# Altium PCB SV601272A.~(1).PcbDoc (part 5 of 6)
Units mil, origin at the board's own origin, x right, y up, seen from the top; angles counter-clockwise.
Board outline 8300 x 9520 mil, 8 copper layers (Top Layer, Signal Layer 1, Signal Layer 2, Signal Layer 3, Signal Layer 4, Signal Layer 5, Signal Layer 6, Bottom Layer), stack 59.2 mil thick; 551 components, 303 nets, 1611 pads, 1923 vias.
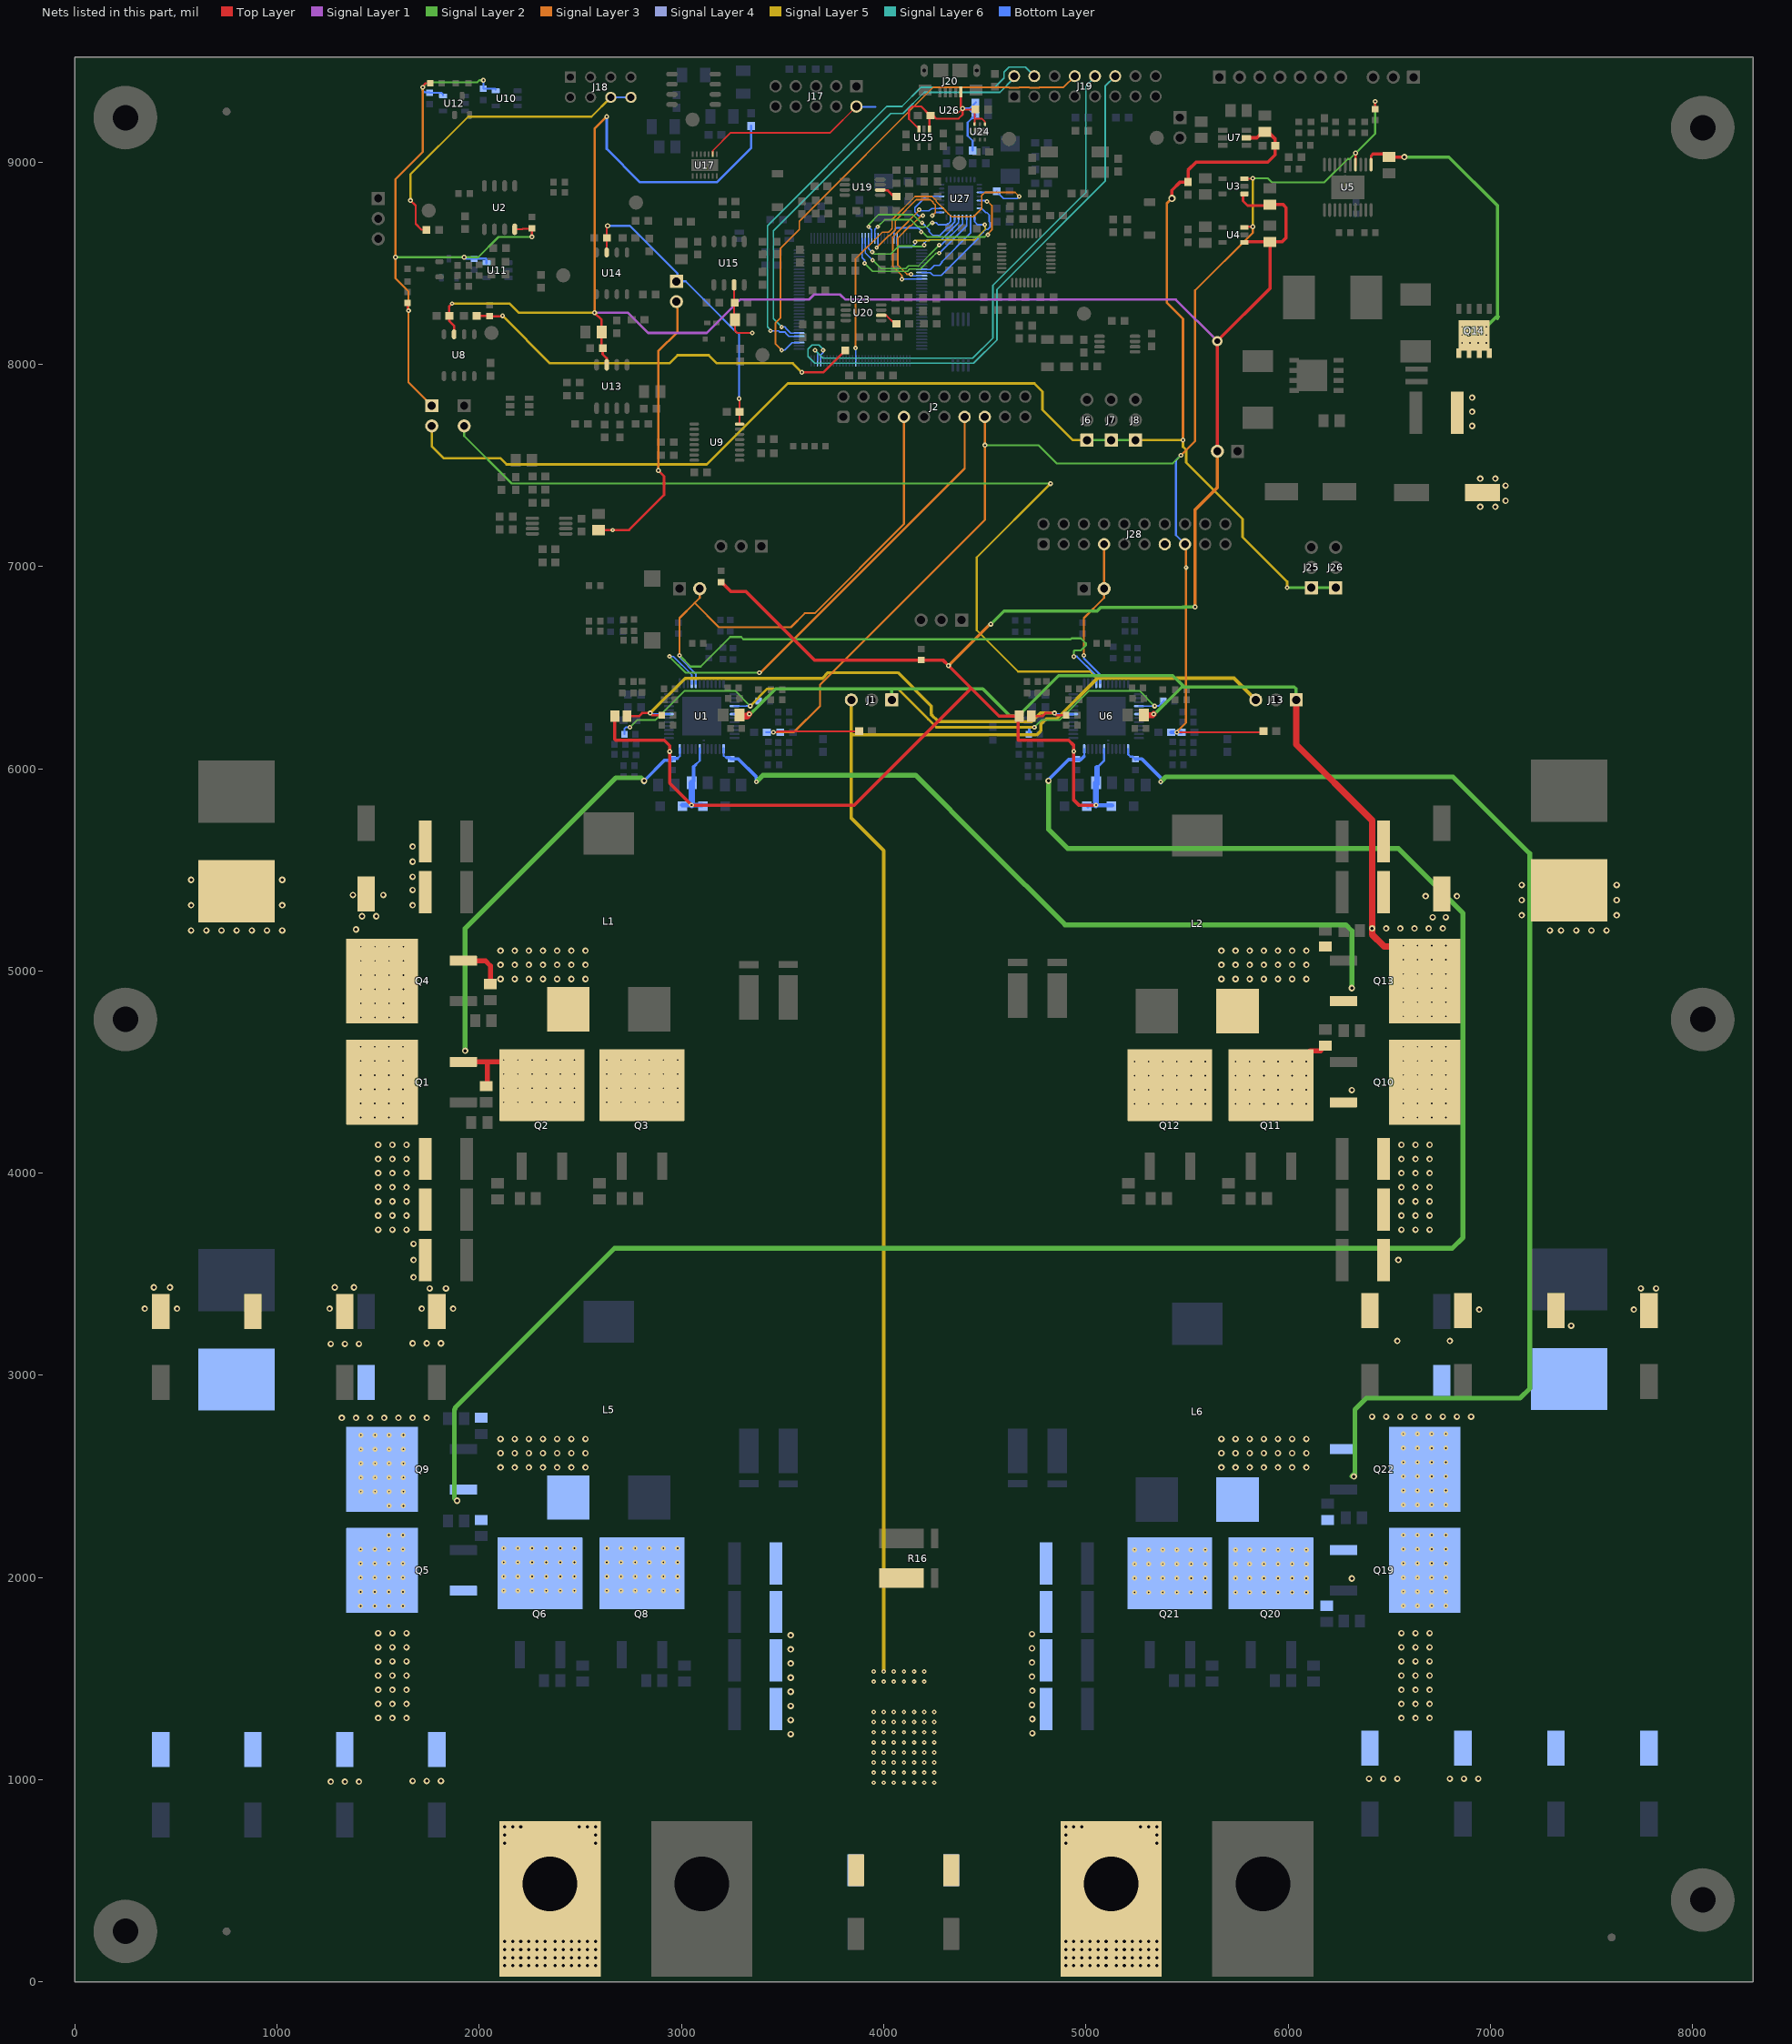
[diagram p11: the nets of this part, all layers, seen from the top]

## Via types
v1: diameter 32, hole 16, Top Layer to Bottom Layer, tented both sides, 622 vias
v2: diameter 24, hole 8, Top Layer to Bottom Layer, 380 vias
v3: diameter 22, hole 8, Top Layer to Bottom Layer, tented both sides, 346 vias
v4: diameter 32, hole 16, Top Layer to Bottom Layer, 237 vias
v5: diameter 24, hole 10, Top Layer to Bottom Layer, tented both sides, 153 vias
v6: diameter 19.68, hole 7.87, Top Layer to Bottom Layer, 70 vias
v7: diameter 24, hole 10, Top Layer to Bottom Layer, 47 vias
v8: diameter 28, hole 8, Top Layer to Bottom Layer, tented top, 24 vias
v9: diameter 22, hole 8, Top Layer to Bottom Layer, 19 vias
v10: diameter 19.68, hole 8, Top Layer to Bottom Layer, 16 vias
v11: diameter 50, hole 28, Top Layer to Bottom Layer, 4 vias
v12: diameter 36, hole 20, Top Layer to Bottom Layer, 2 vias
v13: diameter 26, hole 12, Top Layer to Bottom Layer, 1 vias
v14: diameter 28, hole 12, Top Layer to Bottom Layer, tented both sides, 1 vias
v15: diameter 24, hole 10, Top Layer to Bottom Layer, tented top, 1 vias

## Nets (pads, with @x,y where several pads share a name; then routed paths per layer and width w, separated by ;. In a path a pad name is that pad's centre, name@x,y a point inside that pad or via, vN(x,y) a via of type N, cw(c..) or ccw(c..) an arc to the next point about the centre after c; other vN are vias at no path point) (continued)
SPI_DONE: J19.12 U23.29 | length 2730.5
  Signal Layer 6 w8: v3(3700,8070) 3700,8075 3680,8095 3645,8095 3625,8075 3625,8040 3660,8005 4445,8005 4560,8120 4560,8370 5095,8905 5095,9375 J19.12@5145,9425
  Bottom Layer w6: U23.29@3689.09,8020 3689.09,8046.61 3700,8057.52 v3(3700,8070)
SPI_DRDY: J19.10 U23.30 | length 2500.5
  Signal Layer 6 w8: v3(3660,8070) 3700,8030 4440,8030 4540,8130 4540,8390 5000,8850 5000,9375 5045,9420 J19.10@5045,9425
  Bottom Layer w6: v3(3660,8070) 3672.4,8057.6 U23.30@3672.4,8016.85
SPI_MISO: J19.2 U23.38 | length 2123.7
  Signal Layer 4 w8: J19.2@4645,9405 J19.2@4645,9425
  Signal Layer 6 w8: v3(3495,8185) 3455,8225 3455,8660 4035,9240 4095,9240 4200,9345 4575,9345 4645,9415 J19.2@4645,9425
  Bottom Layer w6: 3520,8175 3540.35,8154.65 U23.38@3581.85,8154.65
  Bottom Layer w8: v3(3495,8185) 3510,8185 3520,8175
SPI_MOSI: J19.4 U23.37 | length 2360.2
  Signal Layer 6 w8: v3(3440,8165) 3440,8170 3425,8185 3425,8685 4015,9275 4090,9275 4185,9370 4550,9370 4595,9415 4595,9445 4620,9470 4700,9470 J19.4@4745,9425
  Bottom Layer w6: 3520,8150 3531.1,8138.9 U23.37@3581.85,8138.9
  Bottom Layer w8: v3(3440,8165) 3480,8165 3485,8160 3510,8160 3520,8150
SPI_SCLK: J19.8 U23.35 | length 2464.4
  Signal Layer 3 w8: v3(3495,8070) 3465,8100 3465,8205 3490,8230 3490,8574.25 3582.87,8667.13 3582.87,8707.87 4245,9370 4619,9370 4621.28,9367.72 4668.72,9367.72 4671,9370 4719,9370 4721.28,9367.72 4768.72,9367.72 4771,9370 4890,9370 J19.8@4945,9425
  Bottom Layer w6: v3(3495,8070) 3510,8070 3547.4,8107.4 U23.35@3581.85,8107.4
SW1: C7.1 L1.1 Q1.3 Q2.4 Q3.4 Q4.3 R22.1 R29.1 U1.24 | length 2634.9
  Top Layer w24: Q1.3@1920.33,4550 2115,4550 Q2.4@2125,4560 ; Q4.3@1935,5050 2030,5050 2055,5025 R29.1@2055,4935 ; R22.1@2040,4425 2040,4550
  Signal Layer 2 w24: v1(1930,4605) 1930,5209.92 2675.08,5955 2800,5955 v1(2815,5940)
  Bottom Layer w9.8: 2980,6050 2991.73,6061.73 U1.24@2991.73,6101.54
  Bottom Layer w16: v1@2815,5930 v1(2815,5940) 2917.56,6042.56 C7.1@2950,6042.56 ; C7.1@2950,6045 2955,6050 2980,6050
  other v1: 2105,4960 2175,4960 2245,4960 2315,4960 2385,4960 2455,4960 2525,4960 2105,5030 2175,5030 2245,5030 2315,5030 2385,5030 2455,5030 2525,5030 2105,5100 2175,5100 2245,5100 2315,5100 2385,5100 2455,5100 2525,5100
  other v2: 2120.63,4349.92 2190.63,4349.92 2260.63,4349.92 2330.63,4349.92 2400.63,4349.92 2470.63,4349.92 2630.63,4349.92 2700.63,4349.92 2770.63,4349.92 2840.63,4349.92 2910.63,4349.92 2980.63,4349.92 2120.63,4419.92 2190.63,4419.92 2260.63,4419.92 2330.63,4419.92 2400.63,4419.92 2470.63,4419.92 2630.63,4419.92 2700.63,4419.92 2770.63,4419.92 2840.63,4419.92 2910.63,4419.92 2980.63,4419.92 2120.63,4489.92 2190.63,4489.92 2260.63,4489.92 2330.63,4489.92 2400.63,4489.92 2470.63,4489.92 2630.63,4489.92 2700.63,4489.92 2770.63,4489.92 2840.63,4489.92 2910.63,4489.92 2980.63,4489.92 2120.63,4559.92 2190.63,4559.92 2260.63,4559.92 2330.63,4559.92 2400.63,4559.92 2470.63,4559.92 2630.63,4559.92 2700.63,4559.92 2770.63,4559.92 2840.63,4559.92 2910.63,4559.92 2980.63,4559.92
SW2: C12.2 L2.2 Q10.3 Q11.4 Q12.4 Q13.3 R33.2 R40.2 U1.13 | length 3975.2
  Top Layer w24: Q11.4@6090,4550 v2(6090,4551.81) 6090,4585 6110,4605 6160,4605 R33.2@6185,4630
  Signal Layer 2 w24: v5(3370,5935) 3403.13,5968.13 4156.87,5968.13 4506.33,5618.67 4506.33,5618.59 4896.8,5228.13 6285,5228.13 6315,5198.13 v4(6315,4915)
  Bottom Layer w9.8: U1.13@3208.27,6101.54 3208.27,6064.32 3222.79,6055
  Bottom Layer w16: 3222.79,6055 3237.56,6055 C12.2@3245,6047.56 3281.91,6047.56 3370,5959.47 v5(3370,5935)
  other v1: 5670,4960 5740,4960 5810,4960 5880,4960 5950,4960 6020,4960 6090,4960 5670,5030 5740,5030 5810,5030 5880,5030 5950,5030 6020,5030 6090,5030 5670,5100 5740,5100 5810,5100 5880,5100 5950,5100 6020,5100 6090,5100
  other v2: 5240,4341.81 5310,4341.81 5380,4341.81 5450,4341.81 5520,4341.81 5590,4341.81 5740,4341.81 5810,4341.81 5880,4341.81 5950,4341.81 6020,4341.81 6090,4341.81 5240,4411.81 5310,4411.81 5380,4411.81 5450,4411.81 5520,4411.81 5590,4411.81 5740,4411.81 5810,4411.81 5880,4411.81 5950,4411.81 6020,4411.81 6090,4411.81 5240,4481.81 5310,4481.81 5380,4481.81 5450,4481.81 5520,4481.81 5590,4481.81 5740,4481.81 5810,4481.81 5880,4481.81 5950,4481.81 6020,4481.81 6090,4481.81 5240,4551.81 5310,4551.81 5380,4551.81 5450,4551.81 5520,4551.81 5590,4551.81 5740,4551.81 5810,4551.81 5880,4551.81 5950,4551.81 6020,4551.81
  other v4: 6315,4410
SW3: C192.1 L5.2 Q5.3 Q6.4 Q8.4 Q9.3 R174.1 R182.1 U6.24 | length 10135.5
  Signal Layer 2 w24: v4(1890,2380) 1876.87,2393.13 1876.87,2831.14 1880.87,2835.14 1880.87,2840.87 2668.13,3628.13 6811.33,3628.13 6865,3681.8 ; v1(4815,5940) 4815,5700.08 4910.08,5605 4973.75,5605 ; 4980,5605 6545,5605 6548.13,5601.87 6548.2,5601.87 6865,5285.08 6865,3681.8 ; 6865,3690 6865,3681.8
  Bottom Layer w9.8: 4991.73,6061.73 U6.24@4991.73,6097.6
  Bottom Layer w16: v1@4810,5940 4915,6045 4975,6045 4991.73,6061.73
  other v1: 2105,2545 2175,2545 2245,2545 2315,2545 2385,2545 2455,2545 2525,2545 2105,2615 2175,2615 2245,2615 2315,2615 2385,2615 2455,2615 2525,2615 2105,2685 2175,2685 2245,2685 2315,2685 2385,2685 2455,2685 2525,2685
  other v2: 2120.63,1934.92 2190.63,1934.92 2260.63,1934.92 2330.63,1934.92 2400.63,1934.92 2470.63,1934.92 2630.63,1934.92 2700.63,1934.92 2770.63,1934.92 2840.63,1934.92 2910.63,1934.92 2980.63,1934.92 2120.63,2004.92 2190.63,2004.92 2260.63,2004.92 2330.63,2004.92 2400.63,2004.92 2470.63,2004.92 2630.63,2004.92 2700.63,2004.92 2770.63,2004.92 2840.63,2004.92 2910.63,2004.92 2980.63,2004.92 2120.63,2074.92 2190.63,2074.92 2260.63,2074.92 2330.63,2074.92 2400.63,2074.92 2470.63,2074.92 2630.63,2074.92 2700.63,2074.92 2770.63,2074.92 2840.63,2074.92 2910.63,2074.92 2980.63,2074.92 2120.63,2144.92 2190.63,2144.92 2260.63,2144.92 2330.63,2144.92 2400.63,2144.92 2470.63,2144.92 2630.63,2144.92 2700.63,2144.92 2770.63,2144.92 2840.63,2144.92 2910.63,2144.92 2980.63,2144.92
SW4: C195.2 L6.1 Q19.3 Q20.4 Q21.4 Q22.3 R185.2 R193.2 U6.13 | length 6144.5
  Signal Layer 2 w24: v5(5370,5935) 5395,5960 6814.92,5960 7195,5579.92 7195,2935.08 ; v4@6315,2500 6330,2515 6330,2830.08 6386.8,2886.87 7146.8,2886.87 7195,2935.08 ; 7195,2935 7195,2935.08
  Bottom Layer w9.8: U6.13@5208.27,6097.6 5208.27,6071.73 5220,6060
  Bottom Layer w12: 5220,6060 5230,6060 C195.2@5245,6045
  Bottom Layer w16: C195.2@5245,6047.56 5277.44,6047.56 5370,5955 v5(5370,5935) v5@5370,5930
  other v1: 6315,1995 5670,2545 5740,2545 5810,2545 5880,2545 5950,2545 6020,2545 6090,2545 5670,2615 5740,2615 5810,2615 5880,2615 5950,2615 6020,2615 6090,2615 5670,2685 5740,2685 5810,2685 5880,2685 5950,2685 6020,2685 6090,2685
  other v2: 5240,1926.81 5310,1926.81 5380,1926.81 5450,1926.81 5520,1926.81 5590,1926.81 5740,1926.81 5810,1926.81 5880,1926.81 5950,1926.81 6020,1926.81 6090,1926.81 5240,1996.81 5310,1996.81 5380,1996.81 5450,1996.81 5520,1996.81 5590,1996.81 5740,1996.81 5810,1996.81 5880,1996.81 5950,1996.81 6020,1996.81 6090,1996.81 5240,2066.81 5310,2066.81 5380,2066.81 5450,2066.81 5520,2066.81 5590,2066.81 5740,2066.81 5810,2066.81 5880,2066.81 5950,2066.81 6020,2066.81 6090,2066.81 5240,2136.81 5310,2136.81 5380,2136.81 5450,2136.81 5520,2136.81 5590,2136.81 5740,2136.81 5810,2136.81 5880,2136.81 5950,2136.81 6020,2136.81 6090,2136.81
  other v4: 6325,2500
SYNC: J2.7 J3.2 U1.41 U6.40 | length 4789.2
  Signal Layer 2 w10: v3(2990,6560) 3045,6505 3095,6505 3241.13,6651.13 3294.89,6651.13 3306.01,6640 4052.23,6640 4101.58,6640 4925,6640 4930,6645 4975,6645 5000,6620 5000,6610 4975,6585 4945,6585 4940,6580 v5(4940,6555)
  Signal Layer 3 w10: v3(2990,6560) 2990,6745 3065,6820 ; J3.2@3090,6890 3090,6845 3065,6820 ; J2.7@4100,7740 4100,7210.28 3658.6,6768.87 3610.11,6768.87 3541.24,6700 3185,6700 3065,6820
  Bottom Layer w8: v3@2985,6565 v3(2990,6560) 2990,6550 3070.38,6469.62 3070.38,6467.28 3070.47,6467.19 U1.41@3070.47,6418.46
  Bottom Layer w9.8: v5@4935,6555 v5(4940,6555) 4955,6555 5044.33,6465.67 5044.33,6465.37 5050.79,6458.91 U6.40@5050.79,6422.4
SYNCIN: J2.13 U1.40 | length 2360.6
  Signal Layer 2 w10: v3(2940,6555) 3020,6475 v5(3385,6475)
  Signal Layer 3 w10: v5@3385,6470 v5(3385,6475) ; v5@3390,6475 4400,7485 J2.13@4400,7740
  Bottom Layer w8: v3(2940,6555) 2960,6555 3050.79,6464.21 U1.40@3050.79,6418.46
SYNCIN2: J28.13
SYNCn: J17.2 U17.2 | length 913.6
  Top Layer w8: U17.2@3154.37,9039.13 3154.37,9055.61 3243.76,9145 3735,9145 J17.2@3865,9275
  Bottom Layer w8: J17.2@3865,9275 3866.5,9273.5 3960,9273.5
SYNCOUT2: J27.2 J28.7 U6.41 | length 757.4
  Signal Layer 3 w10: v5@4990,6570 4990,6745 5090,6845 J27.2@5090,6890 J28.7@5090,7110
  Bottom Layer w9.8: v5@4990,6565 v5(4990,6560) 4990,6545 5062,6473 5062,6472.69 5070.47,6464.22 U6.41@5070.47,6422.4
USB_VBUS: C179.1 C182.1 C187.2 C188.1 J20.1 R149.2 U24.4 U24.6 U25.1 U25.3 U26.6 | length 1197.9
  Top Layer w8: U26.6@4344.69,9243.19 4368.19,9243.19 4387.5,9262.5 v7(4390,9265) ; U24.6@4449.41,9188.39 C179.1@4449.41,9254.41 ; 4450,9215 4485,9215 4500.59,9199.41 U24.4@4500.59,9188.39
  Top Layer w10: U25.3@4174.41,9164.29 4125,9213.7 4125,9260 4140,9275 4185,9275 C182.1@4225,9235 ; U25.1@4225.59,9164.29 4225.59,9220.59 C182.1@4235,9230 ; C182.1@4231.5,9230 C182.1@4235,9230 ; J20.1@4381.18,9357.6 J20.1@4381.18,9347.6 4381.18,9273.82 v7(4390,9265) 4395,9260 C179.1@4453.5,9260 ; v7@4387.5,9262.5 4390,9260 4390,9235 4370,9215 4260,9215 4245,9230 C182.1@4235,9230 ; C179.1@4449.41,9254.41 C179.1@4450,9255 ; C179.1@4450,9250 C179.1@4450,9255 ; C179.1@4455,9260 C179.1@4450,9255
  Bottom Layer w10: v7(4390,9265) 4420,9265 ; R149.2@4440,9056.5 4440,9105 4415,9130 4415,9195 C187.2@4450,9230 ; C187.2@4453.5,9230 4420,9263.5 4420,9265 ; C188.1@4455,9295 4425,9265 4420,9265
USBCLK: U23.92 U27.1 | length 640.8
  Signal Layer 5 w8: v3(4155,8605) 4161.87,8611.87 4189.53,8611.87 ; 4189.53,8611.88 4210.47,8611.88 4221.88,8611.88 4225,8615 ; 4210.47,8611.87 4224.53,8611.87 4227.65,8615 4450,8615 4505,8670 4500,8675 v3(4500,8690)
  Bottom Layer w6: U23.92@4066.1,8623.15 4066.1,8588.9 4075,8580
  Bottom Layer w8: 4075.41,8580.41 4075.75,8580.75 4140.75,8580.75 4160.51,8600.51 v3@4160.51,8610 ; U27.1@4450,8725 4450,8705 4465,8690 v3(4500,8690)
USBD0: U23.81 U27.3 | length 790.3
  Signal Layer 2 w6: v3(3905,8500) 3945.75,8459.25 4114.81,8459.25 4115.56,8460 4118.13,8460 4128.13,8470 4180,8470 4245,8535
  Signal Layer 2 w8: v3@3905,8495 v3(3905,8500) ; 4245,8535 4260,8550 v3(4275,8550)
  Bottom Layer w6: U23.81@3892.87,8623.15 3892.87,8527.13 3900,8520
  Bottom Layer w8: 3900,8520 3905,8515 v3(3905,8500) ; v3(4275,8550) 4410,8685 U27.3@4410,8725 ; U27.3@4409.53,8725 U27.3@4409.53,8726.69
USBD1: U23.82 U27.4 | length 716.2
  Signal Layer 2 w6: v3(3945,8515) 3986.87,8473.13 4109.06,8473.13 4121.68,8485.75 4170.75,8485.75
  Signal Layer 2 w8: 4170.75,8485.75 v3(4275,8590)
  Bottom Layer w6: U23.82@3908.62,8623.15 3908.62,8551.38 3910,8550
  Bottom Layer w8: 3910,8550 v3(3945,8515) ; v3@4270,8585 v3(4275,8590) 4285,8590 4390,8695 U27.4@4390,8715 ; U27.4@4389.84,8715 U27.4@4389.84,8726.69
USBD2: U23.83 U27.5 | length 593.3
  Signal Layer 2 w8: v3(3942.88,8554.87) 3952.75,8545 4035,8545 4075,8585 4142.65,8585 4145.53,8582.13 4192.13,8582.13 v3@4200,8590
  Bottom Layer w6: U23.83@3924.37,8623.15 3924.37,8575.63 3925,8575
  Bottom Layer w8: 3925,8572.75 v3(3942.88,8554.87) ; v3(4200,8589) 4200,8600 4215,8615 4285,8615 4370,8700 U27.5@4370,8715
USBD3: U23.84 U27.6 | length 631.7
  Signal Layer 2 w8: v3(3925,8680) 3925,8690 3975,8740 4145,8740 4185,8700 v3(4190,8700) v3@4195,8695
  Bottom Layer w6: v3(3925,8680) 3940.12,8664.88 U23.84@3940.12,8623.15
  Bottom Layer w8: v3(3925,8680) v3@3930,8680 ; v3(4190,8700) 4225,8665 4225,8655 4242.87,8637.13 4270,8637.13 ; 4270,8635 4275.47,8635 4314.6,8674.13 4321.58,8674.13 4350.47,8703.02 U27.6@4350.47,8726.69
USBD4: U23.85 U27.7 | length 497.8
  Signal Layer 2 w6: 4168.13,8680 4179.07,8680 4180.94,8678.13 4199.06,8678.13 4200.93,8680 4215,8680
  Signal Layer 2 w8: v3(3970,8680) 4005,8715 4133.13,8715 4168.13,8680 ; 4215,8680 4235,8700 v3(4240,8700)
  Bottom Layer w6: U23.85@3955.87,8623.15 3955.87,8665.87 v3(3970,8680)
  Bottom Layer w8: v3@3965,8680 v3(3970,8680) ; v3(4240,8700) 4260,8700 4270,8690 4310,8690 4315,8695 4320,8695 4330,8705 ; 4330.79,8705.79 U27.7@4330.79,8726.69
USBD5: U23.86 U27.9 | length 585.3
  Signal Layer 3 w8: v3(3965.35,8576.75) 4025.85,8637.25 4029.7,8637.25 4034.7,8642.25 4035.64,8642.25 4057.75,8664.36 4057.75,8710.3 4161.58,8814.13 4230.87,8814.13 4244.13,8800.87 4244.13,8798.42 4255,8787.55 4255,8750 v3(4240,8735)
  Bottom Layer w6: v3@3965,8580 3971.61,8586.61 U23.86@3971.61,8623.15
  Bottom Layer w8: v3(4240,8735) 4256.1,8751.1 U27.9@4286.69,8751.1
USBD6: U23.106 U27.10 | length 636.4
  Signal Layer 3 w8: v3(4090,8420) 4090,8440 4045,8485 4045,8629.17 4073.62,8657.79 4073.62,8658.62 4175,8760 v3(4175,8765)
  Bottom Layer w6: v3(4090,8420) 4092.36,8422.36 U23.106@4188.15,8422.36 ; v3(4175,8765) 4181.87,8758.13 4224.16,8758.13 4236.82,8770.79 U27.10@4286.69,8770.79
USBD7: U23.105 U27.13 | length 670.9
  Signal Layer 3 w8: v3(4135,8445) 4115,8445 4070,8490 4070,8625 4130,8685 4135,8685 4185,8735 v3(4194.25,8735)
  Bottom Layer w6: v3(4135,8445) 4141.89,8438.11 U23.105@4188.15,8438.11 ; v3@4195,8735 v3(4194.25,8735) 4172.19,8735 4153.13,8754.07 4153.13,8774.06 4189.07,8810 4190,8810 4209.84,8829.84 U27.13@4286.69,8829.84
USBDIR: U23.104 U27.31 | length 569.8
  Bottom Layer w6: U23.104@4188.15,8453.86 4231.14,8453.86 4240,8445 ; U27.31@4473.31,8770.79 4484.54,8770.79 4505.33,8750 4510,8750
  Bottom Layer w8: 4240,8445 4245,8440 4285,8440 4465,8620 4465,8625 4492.13,8652.13 4492.13,8654.47 4504.78,8667.13 4514.47,8667.13 4527.84,8680.49 4526.94,8681.38 4526.94,8700.4 4521.87,8705.47 4521.87,8738.13 4511.21,8748.79
USBNXT: U23.103 U27.2 | length 396.7
  Bottom Layer w6: U23.103@4188.15,8469.61 4229.61,8469.61 4250,8490 4275,8490 4290,8505
  Bottom Layer w8: 4287.87,8505 4287.87,8507.87 4429.21,8649.21 U27.2@4429.21,8726.69
USBRST: R154.2 U23.18 U27.27 | length 1827.9
  Signal Layer 3 w8: v3(3860,8080) 3860,8520 3993.13,8653.13 4023.13,8653.13 4028.13,8658.13 4029.06,8658.13 4041.87,8670.94 4041.87,8716.87 4155,8830 4240,8830 4260,8810 4260,8805 4306.13,8758.87 4306.13,8758.27 4308.28,8756.12 4308.28,8756 4321,8743.28 4321.72,8743.28 4335,8730 4445,8730 4485,8770 4485,8835 4500,8850 4650,8850 v3(4670,8830)
  Bottom Layer w6: v3(3860,8080) 3861.38,8078.62 U23.18@3861.38,8016.85
  Bottom Layer w8: U27.27@4473.31,8849.53 4554.53,8849.53 R154.2@4559.25,8854.25 ; R154.2@4558.5,8855 R154.2@4559.25,8854.25 ; v3(4670,8830) 4660,8820 4593.5,8820 R154.2@4559.25,8854.25
USBSTP: U23.91 U27.29 | length 756.8
  Signal Layer 2 w8: v3(4185.73,8654.63) 4189.63,8654.63 4190,8655 4215,8630 4500,8630 4510,8640 v3(4515,8640)
  Signal Layer 3 w8: v3(4510,8805) 4515,8805 4535,8785 4535,8665 4515,8645 v3(4515,8640)
  Bottom Layer w6: U23.91@4050.35,8623.15 4050.35,8660.35 4065,8675
  Bottom Layer w8: 4065,8675 4170,8675 4185.73,8659.27 v3(4185.73,8654.63) ; U27.29@4473.31,8810.16 v3@4509.84,8810.16
UVLO: J2.15 J28.15 R4.1 R6.2 R34.1 R45.2 R53.1 R60.2 R87.2 U3.3 U4.3 U5.4 | length 8007.4
  Top Layer w10: v5@3450,6180 v5(3455,6180) 3470,6180 3475,6185 R4.1@3878.5,6185 R4.1@3882.44,6185 ; v5(5450,6180) 5875,6180 R34.1@5880,6185 ; U3.3@5777.24,8917.4 U3.3@5784.13,8917.4 5822.4,8917.4 v5(5825,8920) ; U4.3@5785,8680 v5(5825,8680) ; U5.4@6333.39,8987.2 v5@6333.39,9038.39 ; R53.1@6430,9265 v5(6430,9300)
  Signal Layer 2 w10: v5(4500,7600) 4765,7600 4855,7510 5430,7510 v7(5470,7550) ; v5(5825,8920) 5900,8920 5920,8900 6000,8900 6180.07,8900.07 6295,9015 6304.1,9015 v5(6334.1,9045) 6335,9045 6430,9140 v5(6430,9300)
  Signal Layer 3 w10: v5@3455,6175 3460,6180 3555,6180 3685,6310 3685,6415.56 4500,7230.56 v5(4500,7600) 4500,7715 J2.15@4505,7720 ; v5@5447.5,6180 5495,6227.5 v3(5495,6995) 5495,7080 J28.15@5490,7085 ; v7(5470,7550) 5540,7620 5540,8365 5825,8650 v5(5825,8680)
  Signal Layer 5 w10: v5(5825,8680) v5(5825,8920)
  Bottom Layer w10: R60.2@3417.56,6180 R60.2@3421.5,6180 v5(3455,6180) R6.2@3488.5,6180 R6.2@3490,6180 ; v7(5470,7550) 5445,7525 5445,7155 J28.15@5490,7110
  Bottom Layer w20: R45.2@5421.5,6180 v5(5450,6180) R87.2@5470,6180
V5: C99.2 C111.1 C116.1 C117.1 J14.1 U9.16 U14.7 U15.7 | length 1873.3
  Top Layer w10: U14.7@2630,8553.35 2630,8680 v13(2635,8685) ; C116.1@3255,8310 3260,8305 C117.1@3260,8220 ; U15.7@3260,8390 3260,8308.5 C116.1@3263.5,8305 ; C117.1@3265,8220 3265,8165 3275,8155 v5(3350,8155) ; C99.2@3285,7775 3287.2,7772.8 U9.16@3287.2,7704.57 ; C99.2@3286.5,7775 v5@3286.5,7828.5
  Bottom Layer w10: v13(2635,8685) 2745,8685 2980,8450 J14.1@2980,8410 ; J14.1@2975,8405 J14.1@2980,8410 ; 3280,8155 3285,8150 v5(3285,7830) ; v5(3350,8155) 3275,8155 3110,8320 3020,8410 J14.1@2980,8410
V5.0_Control: C76.1 J6.1 J7.1 J8.1 J14.2 J25.1 J26.1 J37.2 L7.2 R10.1 R164.2 U7.5 | length 8939
  Top Layer w12: L7.2@2590,7180 v3(2660,7180) 2740,7180 2913.65,7353.65 2913.65,7446.35 v7(2885,7475)
  Top Layer w16: v12(5425,8820) 5425,8860 5466.5,8901.5 R164.2@5505,8901.5 5505,8960 5545,9000 5900,9000 5935,9035 R10.1@5935,9075 ; U7.5@5790,9120 U7.5@5793.07,9120 5845,9120 5875,9150 C76.1@5885,9150 ; C76.1@5905,9145 5936.5,9113.5 R10.1@5936.5,9080
  Signal Layer 2 w12: J6.1@5005,7625 J7.1@5125,7625 J8.1@5245,7625 ; v3(5995,6895) J25.1@6115,6895 J26.1@6235,6895
  Signal Layer 3 w12: v7(2885,7475) 2885,8065 2980,8160 J14.2@2980,8315 ; v12(5425,8820) 5400,8795 5400,8305 5480,8225 v5(5480,7625)
  Signal Layer 5 w10: J6.1@5005,7625 J6.1@5015,7625
  Signal Layer 5 w12: J37.2@1765,7695 1765,7595 1825,7535 2105,7535 2120.13,7519.87 2120.3,7519.87 2134.87,7505.3 2134.87,7505 2885,7505 ; v7(2885,7475) 2885,7505 ; J6.1@5005,7625 4935,7625 4785,7775 4785,7865 4745,7905 3525,7905 3125,7505 2885,7505 ; J8.1@5245,7625 v5(5480,7625) 5480,7591.75 5495.87,7575.87 5495.87,7514.13 5775,7235 5775,7145 5995,6925 v3(5995,6895)
V5A: C84.1 C91.2 C93.1 C94.2 J37.1 R90.1 R91.1 U2.8 U10.5 U11.5 U12.5 | length 3298
  Top Layer w10: R90.1@1645,8300 1645,8270 v5(1650,8265) ; v5@1720,9375 1735,9390 R91.1@1757.44,9390 ; U2.8@2175,8667.72 2212.72,8667.72 2215,8670 2260,8670 v5(2260,8630)
  Signal Layer 2 w10: v5(1585,8530) v5(1925,8530) 1995,8530 2095,8630 v5(2260,8630) ; v5(1720,9370) 1745,9395 1990,9395 2000,9405 v5(2020,9405)
  Signal Layer 3 w10: v5(1720,9370) 1720,9050 1585,8915 v5(1585,8530) 1585,8425 1650,8360 v5(1650,8265) 1650,7910 J37.1@1765,7795
  Bottom Layer w10: v5(1720,9370) 1720,9355 1730,9345 C91.2@1755,9345 ; C91.2@1755,9342.56 1812.44,9342.56 1820,9335 U12.5@1820,9330 ; v5(1925,8530) 1932.44,8522.56 C93.1@1975,8522.56 2032.44,8522.56 2035,8520 U11.5@2035,8500 ; v5@2020,9395 C94.2@2020,9362.56 2077.44,9362.56 U10.5@2080,9360
V_HV: C6.1 C18.1 C22.1 C23.1 C24.1 C25.1 C32.1 C33.1 C38.1 C39.1 C40.1 C50.1 C51.1 C52.1 C53.1 C56.1 C57.1 C58.1 C59.1 C60.1 C61.1 C62.1 C63.1 C64.1 C65.1 C66.1 C67.1 C206.1 C207.1 C208.1 C209.1 C210.1 C211.1 C212.1 C213.1 C214.1 C215.1 C216.1 C217.1 J1.1 J9.1 J13.1 Q1.4 Q4.4 Q5.4 Q9.4 Q10.4 Q13.4 Q14.5 Q14.6 Q14.7 Q14.8 Q14.9 Q19.4 Q22.4 T1.1 U1.6 U5.1 U6.6 | length 6399.3
  Top Layer w10: C40.1@6485,9040 C40.1@6500,9025
  Top Layer w13: U5.1@6410.16,8987.2 6410.16,9030.16 6420,9040
  Top Layer w16: 6420,9040 C40.1@6485,9040 ; C40.1@6500,9025 v1(6575,9025)
  Top Layer w30: C33.1@5290,6265 5330,6265 v5(5334.84,6269.84)
  Top Layer w32: C6.1@3285.43,6260 3325,6260 v5(3334.84,6269.84) ; J13.1@6040,6345 J13.1@6040,6340 6040,6120 6415,5745 v1(6415,5210) 6415,5180 6475,5120 Q13.4@6570,5120
  Signal Layer 2 w16: v5(3334.84,6269.84) 3339.84,6269.84 3380,6310 ; 3382.5,6312.5 3465,6395 4040,6395 ; J1.1@4040,6340 4040,6395 ; v5@5339.84,6269.84 5474.18,6404.18 6030.75,6404.18 6040,6395.09 J13.1@6040,6340 ; 5485,6405 5430,6460 4865,6460 4665,6260 4625,6260 4490,6395 4040,6395 ; v1(6575,9025) 6795,9025 7035,8785 7035,8235 ; v8(6980,8185) 7030,8235 7035,8235 ; 7035,8225 7035,8235 ; 7040,8235 7035,8235
  Bottom Layer w9.8: U1.6@3258.46,6269.84 v5(3334.84,6269.84) ; U6.6@5262.4,6269.84 5330.16,6269.84 v5@5335,6265
  other v1: 1265,990 1335,990 1405,990 1670,993.24 1740,993.24 1810,993.24 6400,1005 6470,1005 6540,1005 6800,1005 6870,1005 6940,1005 1500,1305 1570,1305 1640,1305 6560,1305 6630,1305 6700,1305 1500,1375 1570,1375 1640,1375 6560,1375 6630,1375 6700,1375 1500,1445 1570,1445 1640,1445 6560,1445 6630,1445 6700,1445 1500,1515 1570,1515 1640,1515 6560,1515 6630,1515 6700,1515 1500,1585 1570,1585 1640,1585 6560,1585 6630,1585 6700,1585 1500,1655 1570,1655 1640,1655 6560,1655 6630,1655 6700,1655 1500,1725 1570,1725 1640,1725 6560,1725 6630,1725 6700,1725 1320,2790 1390,2790 1460,2790 1530,2790 1600,2790 1670,2790 1740,2790 6415,2795 6485,2795 6555,2795 6625,2795 6695,2795 6765,2795 6835,2795 6905,2795 1265,3155 1335,3155 1405,3155 1670,3158.24 1740,3158.24 1810,3158.24 6540,3170 6800,3170 7400,3245 6945,3325 7710,3325 345,3330 505,3330 1260,3330 1715,3330 1870,3330 1755,3430 1835,3430 7745,3430 7820,3430 390,3435 470,3435 1285,3435 1380,3435 1675,3485 1675,3570 6545,3570 1675,3650 1500,3720 1570,3720 1640,3720 6560,3720 6630,3720 6700,3720 1500,3790 1570,3790 1640,3790 6560,3790 6630,3790 6700,3790 1500,3860 1570,3860 1640,3860 6560,3860 6630,3860 6700,3860 1500,3930 1570,3930 1640,3930 6560,3930 6630,3930 6700,3930 1500,4000 1570,4000 1640,4000 6560,4000 6630,4000 6700,4000 1500,4070 1570,4070 1640,4070 6560,4070 6630,4070 6700,4070 1500,4140 1570,4140 1640,4140 6560,4140 6630,4140 6700,4140 575,5200 650,5200 725,5200 800,5200 875,5200 950,5200 1025,5200 7295,5200 7350,5200 7425,5200 7500,5200 7575,5200 1390,5205 6485,5210 6555,5210 6625,5210 6695,5210 6765,5210 6715,5265 6780,5265 1420,5270 1490,5270 7155,5275 7625,5275 575,5325 1025,5325 1670,5325 7155,5350 7625,5350 6680,5370 6835,5370 1375,5375 1525,5375 1670,5400 7155,5425 7625,5425 575,5450 1025,5450 1670,5465 1670,5540 1670,5615 6950,7295 7025,7295 7075,7325 7075,7400 6950,7435 7025,7435 6910,7695 6910,7765 6910,7835
  other v2: 1412.7,1859.45 1482.7,1859.45 1552.7,1859.45 1622.7,1859.45 6570,1860 6640,1860 6710,1860 6780,1860 1412.7,1929.45 1482.7,1929.45 1552.7,1929.45 1622.7,1929.45 6570,1930 6640,1930 6710,1930 6780,1930 1412.7,1999.45 1482.7,1999.45 1552.7,1999.45 1622.7,1999.45 6570,2000 6640,2000 6710,2000 6780,2000 1412.7,2069.45 1482.7,2069.45 1552.7,2069.45 1622.7,2069.45 6570,2070 6640,2070 6710,2070 6780,2070 1412.7,2139.45 1482.7,2139.45 1552.7,2139.45 1622.7,2139.45 6570,2140 6640,2140 6710,2140 6780,2140 1552.7,2209.45 1622.7,2209.45 6570,2210 6640,2210 6710,2210 6780,2210 1554.19,2354.37 1624.19,2354.37 6570,2360 6640,2360 6710,2360 6780,2360 1414.19,2424.37 1484.19,2424.37 1554.19,2424.37 1624.19,2424.37 6570,2430 6640,2430 6710,2430 6780,2430 1414.19,2494.37 1484.19,2494.37 1554.19,2494.37 1624.19,2494.37 6570,2500 6640,2500 6710,2500 6780,2500 1414.19,2564.37 1484.19,2564.37 1554.19,2564.37 1624.19,2564.37 6570,2570 6640,2570 6710,2570 6780,2570 1414.19,2634.37 1484.19,2634.37 1554.19,2634.37 1624.19,2634.37 6570,2640 6640,2640 6710,2640 6780,2640 1414.19,2704.37 1484.19,2704.37 1554.19,2704.37 1624.19,2704.37 6570,2710 6640,2710 6710,2710 6780,2710 1412.7,4274.45 1482.7,4274.45 1552.7,4274.45 1622.7,4274.45 6570,4275 6640,4275 6710,4275 6780,4275 1412.7,4344.45 1482.7,4344.45 1552.7,4344.45 1622.7,4344.45 6570,4345 6640,4345 6710,4345 6780,4345 1412.7,4414.45 1482.7,4414.45 1552.7,4414.45 1622.7,4414.45 6570,4415 6640,4415 6710,4415 6780,4415 1412.7,4484.45 1482.7,4484.45 1552.7,4484.45 1622.7,4484.45 6570,4485 6640,4485 6710,4485 6780,4485 1412.7,4554.45 1482.7,4554.45 1552.7,4554.45 1622.7,4554.45 6570,4555 6640,4555 6710,4555 6780,4555 1412.7,4624.45 1482.7,4624.45 1552.7,4624.45 1622.7,4624.45 6570,4625 6640,4625 6710,4625 6780,4625 1414.19,4769.37 1484.19,4769.37 1554.19,4769.37 1624.19,4769.37 6570,4775 6640,4775 6710,4775 6780,4775 1414.19,4839.37 1484.19,4839.37 1554.19,4839.37 1624.19,4839.37 6570,4845 6640,4845 6710,4845 6780,4845 1414.19,4909.37 1484.19,4909.37 1554.19,4909.37 1624.19,4909.37 6570,4915 6640,4915 6710,4915 6780,4915 1414.19,4979.37 1484.19,4979.37 1554.19,4979.37 1624.19,4979.37 6570,4985 6640,4985 6710,4985 6780,4985 1414.19,5049.37 1484.19,5049.37 1554.19,5049.37 1624.19,5049.37 6570,5055 6640,5055 6710,5055 6780,5055 1414.19,5119.37 1484.19,5119.37 1554.19,5119.37 1624.19,5119.37 6570,5125 6640,5125 6710,5125 6780,5125
  other v4: 2125,80 2165,80 2205,80 2245,80 2285,80 2325,80 2375,80 2415,80 2455,80 2495,80 2535,80 2575,80 2125,120 2165,120 2205,120 2245,120 2285,120 2325,120 2375,120 2415,120 2455,120 2495,120 2535,120 2575,120 2125,160 2165,160 2205,160 2245,160 2285,160 2325,160 2375,160 2415,160 2455,160 2495,160 2535,160 2575,160 2125,200 2165,200 2205,200 2245,200 2285,200 2325,200 2375,200 2415,200 2455,200 2495,200 2535,200 2575,200 2125,686.27 2575,686.27 2125,726.27 2575,726.27 2125,766.27 2165,766.27 2205,766.27 2495,766.27 2535,766.27 2575,766.27
  other v8: 6860,8105 6900,8105 6940,8105 6980,8105 6860,8145 6900,8145 6940,8145 6980,8145 6860,8185 6900,8185 6940,8185
V_LV: C20.1 C21.1 C26.1 C27.1 C28.1 C29.1 C54.1 C55.1 C68.1 C69.1 C70.1 C71.1 J1.3 J10.1 J13.3 J35.2 R16.2 T2.1 | length 11696.7
  Signal Layer 2 w10: J35.2@1925,7695 1925,7645 2160,7410 v7(4825,7410)
  Signal Layer 2 w16: J1.3@3840,6340 J1.3@3840,6366.13
  Signal Layer 5 w10: v7(4825,7410) 4460,7045 4460,6685 4665,6480 5020,6480 5054.71,6445.29 5055,6445
  Signal Layer 5 w16: J1.3@3840,6340 3840,6165 ; v3(4000,1535) 4000,5595 3840,5755 3840,6165 ; J13.3@5840,6340 5732.13,6447.87 5057.29,6447.87 5054.71,6445.29 4856.55,6247.13 4803.83,6247.13 4777.13,6220.42 4777.13,6187.13 4757.87,6167.87 3842.87,6167.87 3840,6165
  other v1: 3540,1225 4735,1230 3540,1295 4735,1300 3540,1365 4733.24,1370 3540,1435 4735,1440 3540,1505 4733.24,1510 3540,1575 4733.24,1580 3540,1645 4733.24,1650 3540,1715 4733.24,1720
  other v3: 3950,985 4000,985 4050,985 4100,985 4150,985 4200,985 4250,985 3950,1035 4000,1035 4050,1035 4150,1035 4200,1035 4250,1035 3950,1085 4000,1085 4050,1085 4100,1085 4150,1085 4200,1085 4250,1085 3950,1135 4000,1135 4050,1135 4100,1135 4150,1135 4200,1135 4250,1135 3950,1185 4000,1185 4050,1185 4100,1185 4150,1185 4200,1185 4250,1185 3950,1235 4000,1235 4050,1235 4100,1235 4150,1235 4200,1235 4250,1235 3950,1285 4000,1285 4050,1285 4100,1285 4150,1285 4200,1285 4250,1285 3950,1335 4000,1335 4050,1335 4150,1335 4200,1335 4250,1335 3950,1485 4000,1485 4050,1485 4100,1485 4150,1485 4200,1485 3950,1535 4050,1535 4100,1535 4150,1535 4200,1535
  other v4: 4900,80 4940,80 4980,80 5020,80 5060,80 5100,80 5150,80 5190,80 5230,80 5270,80 5310,80 5350,80 4900,120 4940,120 4980,120 5020,120 5060,120 5100,120 5150,120 5190,120 5230,120 5270,120 5310,120 5350,120 4900,160 4940,160 4980,160 5020,160 5060,160 5100,160 5150,160 5190,160 5230,160 5270,160 5310,160 5350,160 4900,200 4940,200 4980,200 5020,200 5060,200 5100,200 5150,200 5190,200 5230,200 5270,200 5310,200 5350,200 4900,686.27 5350,686.27 4900,726.27 5350,726.27 4900,766.27 4940,766.27 4980,766.27 5270,766.27 5310,766.27 5350,766.27
  other v9: 4100,1035 4100,1335
VBAT: C98.1 R52.1 R129.1 | length 2023.1
  Top Layer w12: R52.1@1986.5,8240 C98.1@2055,8240 ; C98.1@2050,8237.44 v7@2117.56,8237.44 ; v7(3595,7960) 3701.5,7960 R129.1@3810,8068.5 R129.1@3810,8073.5
  Signal Layer 5 w12: v7@2120,8235 2350,8005 2940,8005 2980,8045 3135,8045 3175,8005 3550,8005 v7(3595,7960)
  other v7: 2115,8240
VCC: C10.1 C34.1 C36.1 C96.1 C106.1 C107.1 C193.1 D1.2 D2.2 D4.2 D10.2 J4.2 L4.1 R12.2 R14.2 R157.2 R159.2 U1.19 U3.1 U4.1 U6.19 U8.7 U13.7 | length 16250.6
  Top Layer w12: C96.1@1850,8240 1850,8285 v9(1865,8300) ; C96.1@1851.5,8240 1851.5,8213.5 1875,8190 U8.7@1875,8148.35 U8.7@1875,8145 ; v5(2570,8255) 2605,8220 C107.1@2605,8160 2605,8086.5 C106.1@2611.5,8080 ; C106.1@2610,8080 2610,8050 2630,8030 U13.7@2630,7997.28 ; U3.1@5777.24,8842.6 5777.24,8807.76 5800,8785 C34.1@5910,8785
  Top Layer w16: R14.2@2670.47,6255 2670.47,6144.53 2675,6140 2915,6140 2941.54,6113.46 v5(2941.54,6085) 2941.54,5928.46 v5(3050,5820) 3854.42,5820 4429.42,6395 4430,6395 ; R12.2@3195,6925 3242.87,6877.13 3317.87,6877.13 3657.56,6537.44 R157.2@4185,6537.44 4292.56,6537.44 v5(4320,6510) 4570,6260 R159.2@4670.47,6260 4665,6254.53 4665,6140 4915,6140 4940,6115 v3(4940,6085) 4940,5845 4965,5820 v5(5050,5820) ; J4.2@5650,7560 J4.2@5650,7570 v11(5650,8115) 5910,8375 C36.1@5910,8605 ; U4.1@5785,8605 C36.1@5910,8605 ; C34.1@5915,8790 5975,8790 5990,8775 5990,8625 5970,8605 C36.1@5910,8605
  Signal Layer 1 w12: v5(2570,8255) 2735,8255 2835,8155 3125,8155 3290,8320 3630,8320 3655,8345 3785,8345 3810,8320 5445,8320 v11(5650,8115)
  Signal Layer 2 w16: v5@4525,6710 v5(4530,6715) 4595,6780 5055,6780 5073.13,6798.13 5478.13,6798.13 ; v5(5540,6800) 5490,6800 ; 5478.13,6798.13 5488.13,6798.13 5490,6800 ; 5478.13,6798.13 5480,6800 5490,6800
  Signal Layer 3 w12: v5(2570,8255) 2570,9165 v5(2630,9225) ; J4.2@5650,7555 J4.2@5655,7560
  Signal Layer 3 w16: v5(4320,6510) 4525,6715 v5(4530,6715) ; v5(5540,6800) 5540,7280 5650,7390 J4.2@5650,7555
  Signal Layer 5 w12: v9(1865,8300) 2150,8300 2195,8255 v5(2570,8255)
  Bottom Layer w9.8: 3070,6020 3090.16,6039.32 U1.19@3090.16,6101.54 ; 5090.16,6040.16 U6.19@5090.16,6097.6
  Bottom Layer w12: v5(2630,9225) 2630,9065 2795,8900 3175,8900 3345,9070 L4.1@3345,9178.5 ; 5055,6005 5090.16,6040.16
  Bottom Layer w16: C10.1@3050,5930 C10.1@3060,5940 ; 3060,6010 3070,6020
  Bottom Layer w19: C10.1@3060,5940 3060,6009.17
  Bottom Layer w20: D4.2@5010,5815 5015,5820 v5(5050,5820) D10.2@5130,5820
  Bottom Layer w24: D1.2@3005.12,5820 v5(3050,5820) D2.2@3100,5820
  Bottom Layer w25: C193.1@5050,5920 5055,5925 5055,6005
  Bottom Layer w30: v5(5050,5820) 5050,5920 C193.1@5050,5930
  Bottom Layer w32: v5(3050,5820) C10.1@3050,5930
VCCA: C11.1 C194.1 R14.1 R159.1 U1.31 U6.31 | length 2802.7
  Top Layer w12: R14.1@2728.35,6259.53 2789.53,6259.53 2805,6275 v5(2845,6275) 2855,6265 C11.1@2902.44,6265 ; R159.1@4725,6260 R159.1@4729.53,6260 4785,6260 4800,6275 v5(4845,6275) 4855,6265 C194.1@4902.44,6265 C194.1@4905,6265
  Signal Layer 5 w15: v5(2845,6275) 3017.37,6447.37 3697.37,6447.37 3725,6475 4070,6475 4235,6310 4235,6270 ; 4240,6265 4235,6270 ; v5(4845,6275) 4775,6275 4732.37,6232.37 4271.25,6232.37 4233.63,6270 4235,6270
  Bottom Layer w9.8: v5(2845,6275) 2850.16,6269.84 U1.31@2941.54,6269.84
  Bottom Layer w11: v5@4850.16,6269.84 U6.31@4937.6,6269.84
  Bottom Layer w12: v5(4845,6275) v5@4850.16,6269.84
VINX: R1.1 R5.1 R8.1 R43.1 U1.4 U6.4 | length 3306.3
  Signal Layer 2 w9: v5(2745,6205) 2780,6240 2870,6240 3015,6385 3265,6385 v5(3340,6310) ; v5(4745,6205) 4780,6240 4870,6240 5015,6385 5265,6385 v5(5340,6310)
  Signal Layer 5 w12: v5@3340.87,6309.13 v5(3340,6310) 3425,6395 4070,6395 4220,6245 4260,6205 v5(4745,6205)
  Bottom Layer w8: U1.4@3258.46,6309.21 3319.21,6309.21 ; 3320,6310 v5(3340,6310) 3365,6335 R5.1@3382.44,6335 ; U6.4@5262.4,6309.21 5339.21,6309.21 v5(5340,6310) 5360,6310 R43.1@5385,6335
  Bottom Layer w9: R1.1@2717.44,6170 2717.44,6197.44 2725,6205 v5(2745,6205)
  Bottom Layer w12: R8.1@4720,6170 4720,6205 v5(4745,6205)
Vocm1: C131.1 U19.2 | length 95.9
  Top Layer w12: U19.2@3980,8860 4020,8860 4050,8830 C131.1@4063.5,8830
Vocm2: C132.1 U20.2 | length 94.9
  Top Layer w9.8: U20.2@3987.6,8242.2 4012.8,8242.2 4055,8200 C132.1@4063.5,8200 C132.1@4065,8200
VREF: J18.6 J18.8 R84.2 | length 1578.7
  Top Layer w10: v5@1665,8810 v5(1660,8810) 1685,8785 1685,8695 1715,8665 R84.2@1738.5,8665 ; R84.2@1740,8665 R84.2@1740,8670
  Signal Layer 5 w10: v5(1660,8810) 1660,8940 1945,9225 2555,9225 J18.6@2650,9320
  Bottom Layer w10: J18.6@2650,9320 J18.8@2750,9320
pads on no net: FID1.1 FID2.1 FID3.1 FID4.1 FID5.1 FID6.1 H1.1 H2.1 H3.1 H4.1 H5.0 H6.0 H7.0 H8.0 H9.1 H10.1 H11.0 H12.0 J17.1 J17.10 J20.6 J20.7 J20.8 J20.9 J20.10 J20.11 L1.MP L2.MP L5.MP L6.MP LBL1.0 Q16.3 S3.4 S3.5 S3.6 U1.3 U1.5 U1.7 U1.16 U1.21 U1.32 U2.1 U2.2 U2.3 U3.4 U4.4 U5.11 U6.3 U6.5 U6.7 U6.16 U6.21 U6.32 U8.1 U8.5 U8.8 U9.12 U9.13 U9.14 U10.1 U14.1 U14.5 U14.8 U15.1 U15.5 U15.8 U16.1 U16.3 U16.7 U16.8 U17.5 U17.11 U21.24 U22.1 U22.3 U22.7 U22.8 U23.1 U23.2 U23.3 U23.4 U23.5 U23.6 U23.11 U23.12 U23.13 U23.14 U23.15 U23.19 U23.20 U23.21 U23.22 U23.23 U23.24 U23.25 U23.27 U23.31 U23.32 U23.40 U23.41 U23.42 U23.43 U23.44 U23.45 U23.46 U23.49 U23.50 U23.53 U23.54 U23.56 U23.57 U23.60 U23.61 U23.62 U23.63 U23.65 U23.71 U23.72 U23.73 U23.74 U23.75 U23.76 U23.77 U23.78 U23.93 U23.94 U23.95 U23.96 U23.102 U23.107 U23.108 U23.109 U23.110 U23.116 U23.117 U23.118 U23.119 U23.120 U23.121 U23.123 U23.124 U23.125 U23.126 U23.127 U23.128 U24.5 U24.7@4457.28,9150 U24.7@4492.72,9150 U26.5 U27.12 U27.15 U27.16 U27.17
copper on no net: | length 2209.7
  Top Layer w10: v5@2505,6880 v5(2500,6880) 2500,6935 2707.13,7142.13 2791.85,7142.13 3029.72,7380 3425,7380 3510,7465 v5(3510,7510) ; 3385,7770 3390,7775 ; 3390,7778.5 3390,7775 ; 3395,7700 3390,7705 3390,7775 ; v5(3440,7775) 3390,7775 ; 3456.5,7700 v5(3510,7700) v5@3515,7700
  Signal Layer 3 w10: 2090,8229.57 2090.13,8229.7 2090.13,8250.3 2090,8250.43 ; v5(3510,7510) v5(3510,7700)
  Signal Layer 6 w10: 2452.4,4707.87 2455.28,4705
  Bottom Layer w10: 3060,7790 3425,7790 v5(3440,7775)
  Bottom Layer w12: 1850,8522.24 1850,8597.44 1850,8600
  other v1: 4895,1020 1320,5205

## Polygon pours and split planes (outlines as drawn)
PGND on Bottom Layer "PGND_L08_P6203" (solid, remove dead copper, pour order 6203): 0,0 0,9520 8300,9520 8300,0
AGND on Bottom Layer "AGND_L08_P6202" (solid, remove dead copper, pour order 6202): 2469.97,9500 1425,9500 1425,6070 6615,6070 6615,9500
V_LV on Bottom Layer "V_LV_L08_P6200" (solid, remove dead copper, pour order 6200): 5465.14,30.26 4674.74,30.26 4340,365 3810,365 3423.14,751.86 3423.14,2270 4888.14,2270 4888.14,1320 5465.14,743
AGND on Bottom Layer "AGND_L08_P6185" (solid, remove dead copper, pour order 6185): 4739.81,5940 4739.81,6424.81 4895,6580 5465,6580 5465,5985 5590,5985 5590,6690 4615,6690 4615,5940
AGND on Bottom Layer "AGND_L08_P6186" (solid, remove dead copper, pour order 6186): 2739.81,5940 2739.81,6424.81 2895,6580 3465,6580 3465,5985 3590,5985 3590,6690 2615,6690 2615,5940
I_TOTAL on Bottom Layer "I_TOTAL_L08_P6190" (solid, remove dead copper, pour order 6190): 3465,5235 4710,5235 4710,4755 3465,4755
SW2 on Bottom Layer "SW2_L08_P6193" (solid, remove dead copper, pour order 6193): 5520,5150 5520,4690 5483.67,4653.67 5103.67,4653.67 5070,4620 5070,4275 5111.33,4233.67 6313.67,4233.67 6350,4270 6350,5160 6316.33,5193.67 5563.67,5193.67
SW1 on Bottom Layer "SW1_L08_P6195" (solid, remove dead copper, pour order 6195): 3180,4275 3180,4605 3130,4655 2715,4655 2670.56,4699.44 2670.56,5134.44 2620,5185 1885,5185 1850.56,5150.56 1850.56,4299.44 1925,4225 3130,4225
V_HV on Bottom Layer "V_HV_L08_P6197" (solid, remove dead copper, pour order 6197): 1840,3360 1120,3360 1120,5550 1840,5550
V_HV on Bottom Layer "V_HV_L08_P6196" (solid, remove dead copper, pour order 6196): 7080,3360 6365,3360 6365,5550 7080,5550
V_HV on Bottom Layer "V_HV_L08_P6199" (solid, remove dead copper, pour order 6199): 1840,945 310,945 310,3135 1840,3135
SW4 on Bottom Layer "SW4_L08_P6192" (solid, remove dead copper, pour order 6192): 5520,2735 5520,2275 5483.67,2238.67 5103.67,2238.67 5070,2205 5070,1860 5111.33,1818.67 6313.67,1818.67 6350,1855 6350,2745 6316.33,2778.67 5563.67,2778.67
SW3 on Bottom Layer "SW3_L08_P6194" (solid, remove dead copper, pour order 6194): 3180,1860 3180,2190 3130,2240 2715,2240 2670.56,2284.44 2670.56,2719.44 2620,2770 1885,2770 1850.56,2735.56 1850.56,1884.44 1925,1810 3130,1810
V_LV on Bottom Layer "V_LV_L08_P6187" (solid, remove dead copper, pour order 6187): 3925,1535 4275,1535 4275,685 3925,685
NetL5_1 on Bottom Layer "NETL5_1_L08_P6188" (solid, remove dead copper, pour order 6188): 2720,2275 3370,2275 3395,2300 3395,2740 3370,2765 2720,2765 2700,2745 2700,2295
NetL6_2 on Bottom Layer "NETL6_2_L08_P6189" (solid, remove dead copper, pour order 6189): 4830,2265 5460,2265 5490,2295 5490,2745 5460,2775 4830,2775 4800,2745 4800,2295
I_TOTAL on Bottom Layer "I_TOTAL_L08_P6191" (solid, remove dead copper, pour order 6191): 3535,2830 4665,2830 4710,2785 4710,2340 3465,2340 3465,2760
V_HV on Bottom Layer "V_HV_L08_P6201" (solid, remove dead copper, pour order 6201): 7935,945 6365,945 6365,3135 7935,3135
I_TOTAL on Bottom Layer "I_TOTAL_L08_P6198" (solid, pour order 6198): 4675,5240 4675,2335 3780,2335 3780,5240
PGND on Signal Layer 1 "PGND_L02_P6086" (solid, remove dead copper, pour order 6086): 0,0 0,9520 8300,9520 8300,0
AGND on Signal Layer 1 "AGND_L02_P6085" (solid, remove dead copper, pour order 6085): 2469.97,9500 1425,9500 1425,6070 6615,6070 6615,9500
I_TOTAL on Signal Layer 1 "I_TOTAL_L02_P6083" (solid, remove dead copper, pour order 6083): 4730,2340 3460,2340 3460,2820 4730,2820
I_TOTAL on Signal Layer 1 "I_TOTAL_L02_P6084" (solid, remove dead copper, pour order 6084): 4730,4755 3460,4755 3460,5235 4730,5235
SW1 on Signal Layer 1 "SW1_L02_P6069" (solid, remove dead copper, pour order 6069): 2120,4620 2490,4620 2505,4605 2505,4265 2485,4245 2115,4245 2095,4265 2095,4595
SW1 on Signal Layer 1 "SW1_L02_P6067" (solid, remove dead copper, pour order 6067): 2630,4620 2980,4620 3010,4590 3010,4270 2985,4245 2625,4245 2600,4270 2600,4590
SW2 on Signal Layer 1 "SW2_L02_P6071" (solid, remove dead copper, pour order 6071): 5728.58,4618.58 6101.42,4618.58 6120,4600 6120,4260 6103.58,4243.58 5726.42,4243.58 5710,4260 5710,4600
SW2 on Signal Layer 1 "SW2_L02_P6073" (solid, remove dead copper, pour order 6073): 5228.58,4618.58 5601.42,4618.58 5620,4600 5620,4260 5603.58,4243.58 5226.42,4243.58 5210,4260 5210,4600
V_HV on Signal Layer 1 "V_HV_L02_P6079" (solid, remove dead copper, pour order 6079): 1710,5155 1710,4745 1335,4745 1335,5155
V_HV on Signal Layer 1 "V_HV_L02_P6080" (solid, remove dead copper, pour order 6080): 1710,4655 1710,4245 1335,4245 1335,4655
V_HV on Signal Layer 1 "V_HV_L02_P6078" (solid, remove dead copper, pour order 6078): 6855,5155 6855,4745 6480,4745 6480,5155
V_HV on Signal Layer 1 "V_HV_L02_P6077" (solid, remove dead copper, pour order 6077): 6850,4655 6850,4245 6475,4245 6475,4655
V_HV on Signal Layer 1 "V_HV_L02_P6074" (solid, remove dead copper, pour order 6074): 6850,2240 6850,1830 6475,1830 6475,2240
V_HV on Signal Layer 1 "V_HV_L02_P6081" (solid, remove dead copper, pour order 6081): 6855,2740 6855,2330 6480,2330 6480,2740
V_HV on Signal Layer 1 "V_HV_L02_P6075" (solid, remove dead copper, pour order 6075): 1710,2240 1710,1830 1335,1830 1335,2240
V_HV on Signal Layer 1 "V_HV_L02_P6076" (solid, remove dead copper, pour order 6076): 1710,2740 1710,2330 1335,2330 1335,2740
SW4 on Signal Layer 1 "SW4_L02_P6072" (solid, remove dead copper, pour order 6072): 5228.58,2203.58 5601.42,2203.58 5620,2185 5620,1845 5603.58,1828.58 5226.42,1828.58 5210,1845 5210,2185
SW4 on Signal Layer 1 "SW4_L02_P6070" (solid, remove dead copper, pour order 6070): 5728.58,2203.58 6101.42,2203.58 6120,2185 6120,1845 6103.58,1828.58 5726.42,1828.58 5710,1845 5710,2185
SW3 on Signal Layer 1 "SW3_L02_P6066" (solid, remove dead copper, pour order 6066): 2630,2205 2980,2205 3010,2175 3010,1855 2985,1830 2625,1830 2600,1855 2600,2175
SW3 on Signal Layer 1 "SW3_L02_P6068" (solid, remove dead copper, pour order 6068): 2120,2205 2490,2205 2505,2190 2505,1850 2485,1830 2115,1830 2095,1850 2095,2180
V_LV on Signal Layer 1 "V_LV_L02_P6082" (solid, remove dead copper, pour order 6082): 3925,1560 4275,1560 4275,935 3925,935
PGND on Signal Layer 2 "PGND_L03_P6116" (solid, remove dead copper, pour order 6116): 0,0 0,9520 8300,9520 8300,0
AGND on Signal Layer 2 "AGND_L03_P6115" (solid, remove dead copper, pour order 6115): 2469.97,9500 1425,9500 1425,6070 6615,6070 6615,9500
SW4 on Signal Layer 2 "SW4_L03_P6109" (solid, remove dead copper, pour order 6109): 5543.67,2778.67 6316.33,2778.67 6350,2745 6350,2155.01 5520.07,2154.96 5520,2755
V_LV on Signal Layer 2 "V_LV_L03_P6114" (solid, remove dead copper, pour order 6114): 5462,30.26 4750,30.26 4415.26,365 3800,365 3420,745 3420,2135 4885,2135 4885,1320 5462,743
SW4 on Signal Layer 2 "SW4_L03_P6104" (solid, remove dead copper, pour order 6104): 3200,1625 3200,1295 3230,1265 4320,1265 4350,1295 4350,1625 4320.49,1654.52 3230,1654.99
NetL5_1 on Signal Layer 2 "NETL5_1_L03_P6101" (solid, remove dead copper, pour order 6101): 2730,2765 3275,2765 3300,2740 3300,2270 3280,2250 2720,2250 2700,2270 2700,2735
NetL6_2 on Signal Layer 2 "Signal Layer 2-No Net 7" (solid, remove dead copper, pour order 6102): 4910,2765 5480,2765 5495,2750 5495,2270 5475,2250 4915,2250 4895,2270 4895,2750
I_TOTAL on Signal Layer 2 "I_TOTAL_L03_P6111" (solid, remove dead copper, pour order 6111): 3535,2830 4665,2830 4710,2785 4710,2340 3465,2340 3465,2760
NetL2_1 on Signal Layer 2 "NETL2_1_L03_P6099" (solid, remove dead copper, pour order 6099): 4910,5180 5480,5180 5495,5165 5495,4685 5475,4665 4915,4665 4910,4670
V_HV on Signal Layer 2 "V_HV_L03_P6089" (solid, remove dead copper, pour order 6089): 1805,4750 1380,4750 1330,4800 1330,5166.54 1805,5166.54
V_HV on Signal Layer 2 "V_HV_L03_P6094" (solid, remove dead copper, pour order 6094): 1806,4225 1330.27,4225 1330.27,4610 1330.27,4614.09 1365,4648.82 1368.82,4645 1806,4645
SW1 on Signal Layer 2 "SW1_L03_P6107" (solid, remove dead copper, pour order 6107): 2643.26,5186.74 1886.74,5186.74 1850,5150 1850,4580 2670,4580 2670,5160
SW2 on Signal Layer 2 "SW2_L03_P6110" (solid, remove dead copper, pour order 6110): 5543.67,5193.67 6316.33,5193.67 6350,5160 6350,4570.01 5520.07,4569.96 5520,5170
SW2 on Signal Layer 2 "SW2_L03_P6103" (solid, remove dead copper, pour order 6103): 5200,4590 5200,4260 5230,4230 6320,4230 6350,4260 6350,4590 6320.49,4619.52 5230,4619.99
SW1 on Signal Layer 2 "SW1_L03_P6105" (solid, remove dead copper, pour order 6105): 3020,4250 3020,4590 2990,4620 1872.94,4620 1850.56,4594.06 1850.56,4249.44 1875,4225 2995,4225
NetD6_2 on Signal Layer 2 "Signal Layer 2-No Net 3" (solid, pour order 6087): 6215,7820 5750,7820 5750,8095 6215,8095
V_HV on Signal Layer 2 "V_HV_L03_P6097" (solid, remove dead copper, pour order 6097): 7080,7220 6850,7220 6850,7525 6800,7575 6800,7920 6800,7945 6775,7970 6775,8240 7080,8240
I_TOTAL on Signal Layer 2 "I_TOTAL_L03_P6112" (solid, remove dead copper, pour order 6112): 4670,4590 3510,4590 3460,4640 3460,5250 4725,5250 4725,4645
NetL1_2 on Signal Layer 2 "NETL1_2_L03_P6100" (solid, remove dead copper, pour order 6100): 2730,5180 3275,5180 3300,5155 3300,4685 3280,4665 2720,4665 2700,4685 2700,5150
SW3 on Signal Layer 2 "SW3_L03_P6106" (solid, remove dead copper, pour order 6106): 3020,1285 3020,1625 2990,1655 1872.94,1655 1850.56,1629.06 1850.56,1284.44 1875,1260 2995,1260
SW3 on Signal Layer 2 "SW3_L03_P6108" (solid, remove dead copper, pour order 6108): 2643.26,2771.74 1886.74,2771.74 1850,2735 1850,2165 2670,2165 2670,2745
V_HV on Signal Layer 2 "V_HV_L03_P6095" (solid, remove dead copper, pour order 6095): 1806,1810 1330.27,1810 1330.27,2195 1330.27,2199.09 1365,2233.82 1368.82,2230 1806,2230
V_HV on Signal Layer 2 "V_HV_L03_P6090" (solid, remove dead copper, pour order 6090): 1805,2335 1380,2335 1330,2385 1330,2751.54 1805,2751.54
V_HV on Signal Layer 2 "V_HV_L03_P6096" (solid, remove dead copper, pour order 6096): 7080,7220 6850,7220 6850,7525 6800,7575 6800,7920 6800,7945 6775,7970 6775,8240 7080,8240
V_LV on Signal Layer 2 "V_LV_L03_P6098" (solid, remove dead copper, pour order 6098): 3925,1535 4275,1535 4275,685 3925,685
V_HV on Signal Layer 2 "V_HV_L03_P6091" (solid, remove dead copper, pour order 6091): 6960,2340 6535,2340 6485,2390 6485,2756.54 6960,2756.54
V_HV on Signal Layer 2 "V_HV_L03_P6093" (solid, remove dead copper, pour order 6093): 6966,1810 6490.27,1810 6490.27,2195 6490.27,2199.09 6525,2233.82 6528.82,2230 6966,2230
V_HV on Signal Layer 2 "V_HV_L03_P6088" (solid, remove dead copper, pour order 6088): 6960,4755 6535,4755 6485,4805 6485,5171.54 6960,5171.54
V_HV on Signal Layer 2 "V_HV_L03_P6092" (solid, remove dead copper, pour order 6092): 6966,4225 6490.27,4225 6490.27,4610 6490.27,4614.09 6525,4648.82 6528.82,4645 6966,4645
V_LV on Signal Layer 2 "V_LV_L03_P6113" (solid, remove dead copper, pour order 6113): 2885,3605 1420,3605 1420,4675 2885,4675 2885,3735
PGND on Top Layer "PGND_L01_P6065" (solid, remove dead copper, pour order 6065): 0,0 0,9520 8320,9520 8320,0
AGND on Top Layer "AGND_L01_P6064" (solid, remove dead copper, pour order 6064): 2469.97,9500 1425,9500 1425,6070 6615,6070 6615,9500
V_LV on Top Layer "V_LV_L01_P6061" (solid, remove dead copper, pour order 6061): 5462,30.26 4699.74,30.26 4365,365 3800,365 3420,745 3420,2075 4885,2075 4885,1295 5462,718
NetL5_1 on Top Layer "NETL5_1_L01_P6048" (solid, remove dead copper, pour order 6048): 2720,2275 3370,2275 3395,2300 3395,2740 3370,2765 2720,2765 2700,2745 2700,2295
I_TOTAL on Top Layer "I_TOTAL_L01_P6053" (solid, remove dead copper, pour order 6053): 3460,4755 3460,5235 4730,5235 4730,4755
V_HV on Top Layer "V_HV_L01_P6060" (solid, remove dead copper, pour order 6060): 1840,945 1000,945 1000,3135 1840,3135
SW3 on Top Layer "SW3_L01_P6058" (solid, remove dead copper, pour order 6058): 3180,1845 3180,2205 3143.26,2241.74 2716.74,2241.74 2670,2288.49 2670,2755 2653.26,2771.74 1886.74,2771.74 1850,2735 1850,1850 1888.26,1811.74 3146.74,1811.74
SW4 on Top Layer "SW4_L01_P6056" (solid, remove dead copper, pour order 6056): 5520,2735 5520,2285 5473.67,2238.67 5108.67,2238.67 5070,2200 5070,1865 5116.33,1818.67 6308.67,1818.67 6350,1860 6350,2745 6316.33,2778.67 5563.67,2778.67
NetC42_1 on Top Layer "NETC42_1_L01_P6041" (solid, remove dead copper, pour order 6041): 5715,7275 5715,7790 6200,7790 6200,7665 6200,7605 6070,7475 6065,7470 6065,7275
V_HV on Top Layer "V_HV_L01_P6045" (solid, remove dead copper, pour order 6045): 7050,7220 6870,7220 6850,7240 6850,7524.74 6799.74,7575 6799.74,7920 6799.74,7945 6774.74,7970 6774.74,8204.74 6810,8240 7050,8240 7079.74,8210.26 7079.74,7249.74
NetD6_2 on Top Layer "NETD6_2_L01_P6042" (solid, remove dead copper, pour order 6042): 6215,7850 6215.01,8149.99 6150,8215 6150,8435 6115,8470 6000,8470 5957.5,8427.5 5957.5,8242.5 5935,8220 5790,8220 5750,8180 5750,7850 5780,7820 6185,7820
NetD7_2 on Top Layer "Top Layer-No Net 1" (solid, remove dead copper, pour order 6038): 6530,8120 6730,8120 6750,8100 6750,7990 6725,7965 6560,7965 6510,8015 6510,8100
NetC41_1 on Top Layer "NETC41_1_L01_P6040" (solid, remove dead copper, pour order 6040): 6295,8230 6295,8440 6330,8475 7060,8475 7080,8455 7080,8285 7055,8260 6800,8260 6740,8200 6705,8200 6325,8200
SW1 on Top Layer "SW1_L01_P6057" (solid, remove dead copper, pour order 6057): 3180,4260 3180,4620 3143.26,4656.74 2716.74,4656.74 2670,4703.49 2670,5170 2653.26,5186.74 1886.74,5186.74 1850,5150 1850,4265 1888.26,4226.74 3146.74,4226.74
NetL1_2 on Top Layer "NETL1_2_L01_P6047" (solid, remove dead copper, pour order 6047): 2720,4690 3370,4690 3395,4715 3395,5155 3370,5180 2720,5180 2700,5160 2700,4710
V_HV on Top Layer "V_HV_L01_P6063" (solid, remove dead copper, pour order 6063): 1840,3210 145,3210 145,5550 1840,5550
V_HV on Top Layer "V_HV_L01_P6062" (solid, remove dead copper, pour order 6062): 7845,3210 6365,3210 6365,5550 7845,5550
SW2 on Top Layer "SW2_L01_P6055" (solid, remove dead copper, pour order 6055): 5520,5150 5520,4700 5473.67,4653.67 5108.67,4653.67 5070,4615 5070,4280 5116.33,4233.67 6308.67,4233.67 6350,4275 6350,5160 6316.33,5193.67 5563.67,5193.67
NetL2_1 on Top Layer "NETL2_1_L01_P6049" (solid, remove dead copper, pour order 6049): 4830,4680 5460,4680 5490,4710 5490,5160 5460,5190 4830,5190 4800,5160 4800,4710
